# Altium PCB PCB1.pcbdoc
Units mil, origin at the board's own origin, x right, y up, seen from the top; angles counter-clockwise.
Board outline 5270 x 5080 mil, 2 copper layers (Top Layer, Bottom Layer); 23 components, 26 nets, 116 pads, 268 vias.
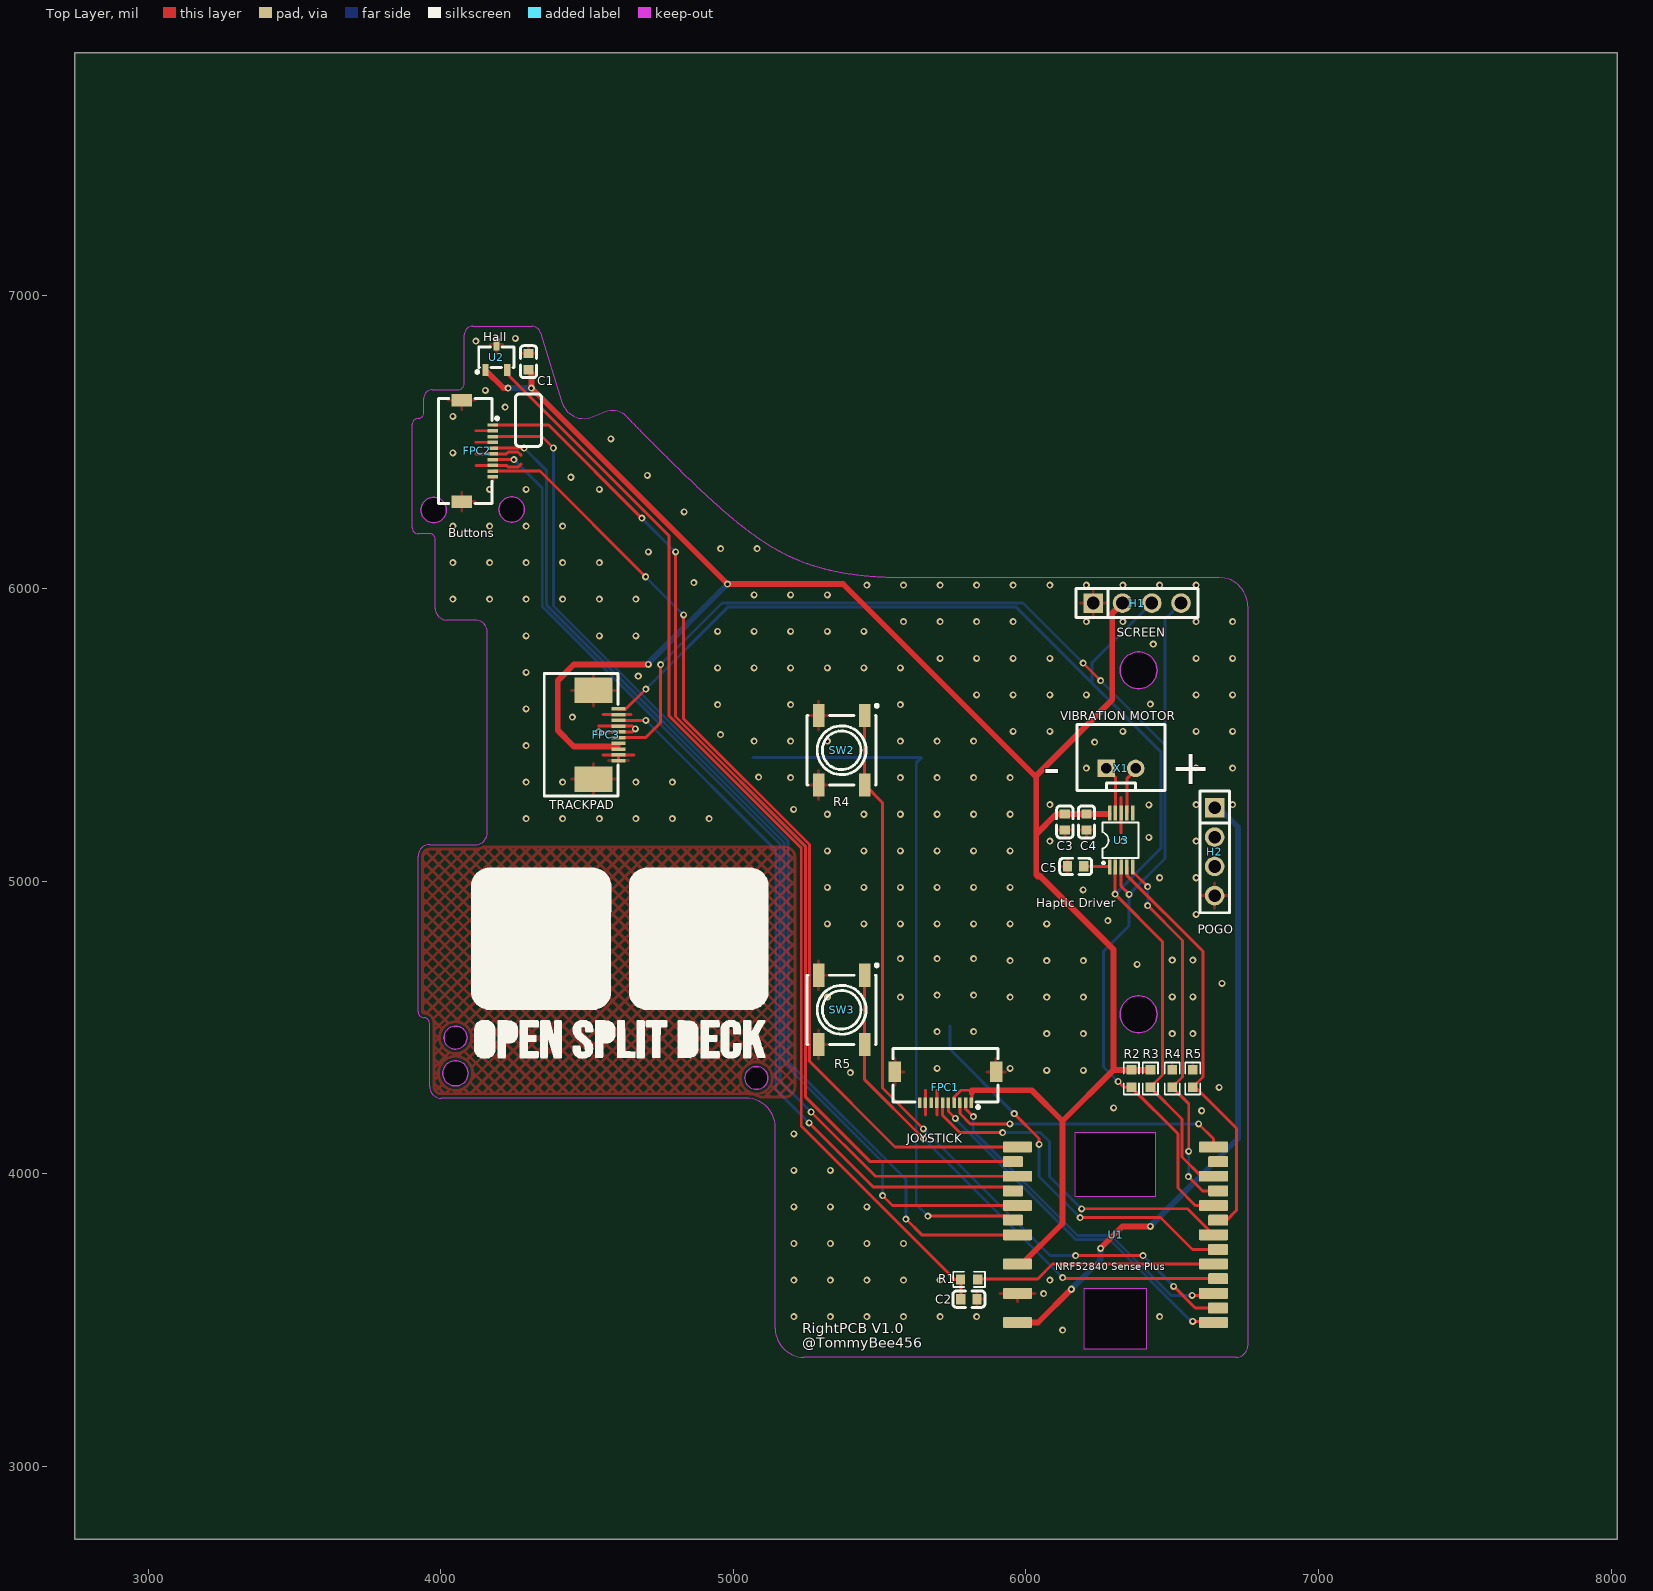
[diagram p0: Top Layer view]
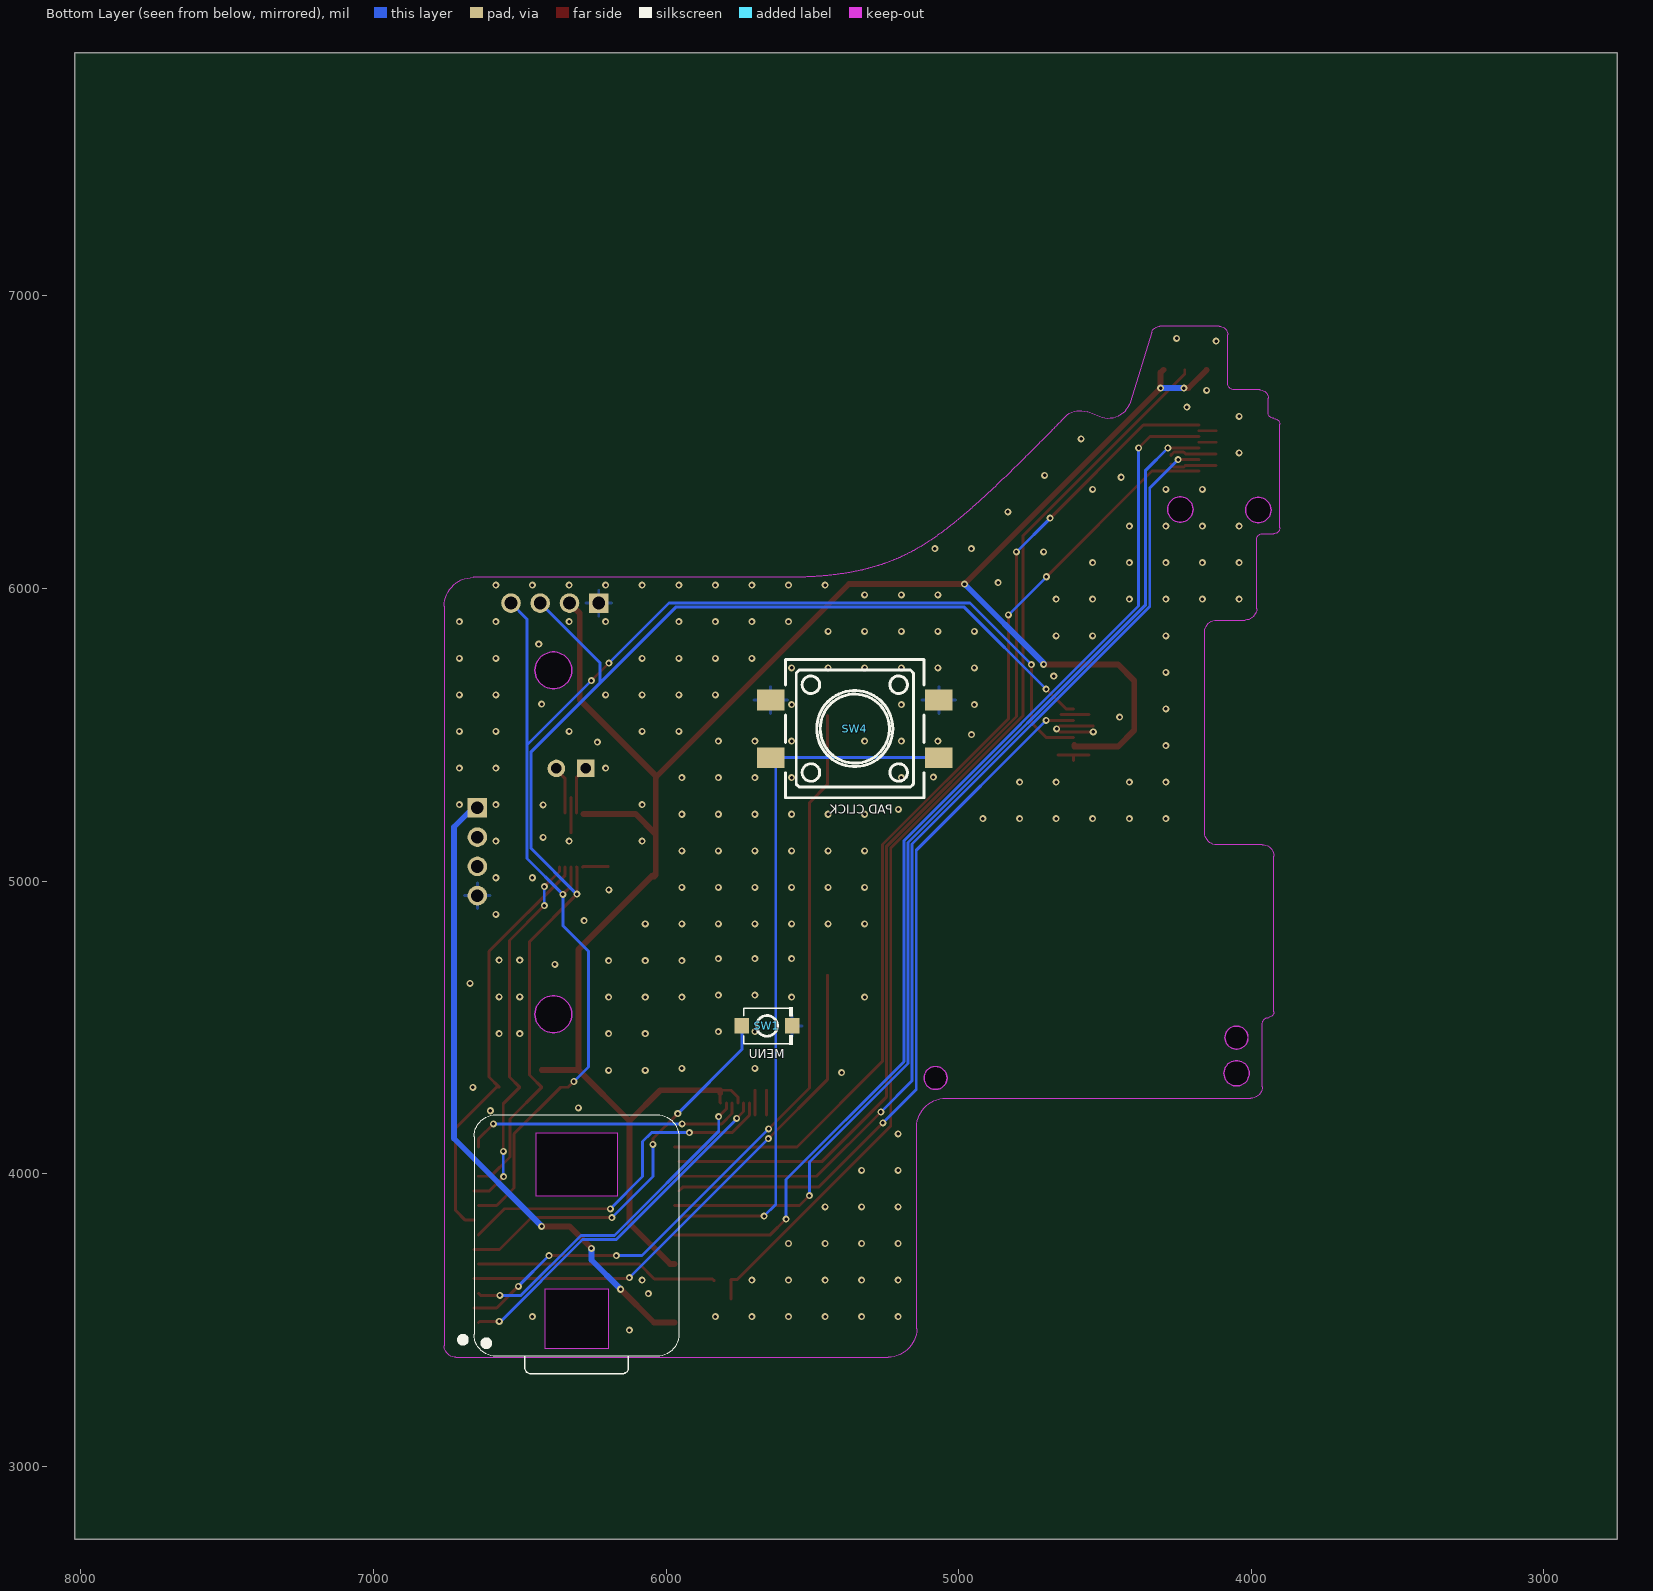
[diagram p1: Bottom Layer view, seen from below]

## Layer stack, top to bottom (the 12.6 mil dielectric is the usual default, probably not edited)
Top Layer: signal copper (thickness not stored)
Dielectric: dielectric 12.6, FR-4, Dk 4.8
Bottom Layer: signal copper (thickness not stored)

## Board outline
8020,2750 2750,2750 2750,7830 8020,7830
cut-out: 5118.27,4327 cw(c5078.9,4327) 5039.53,4327 cw(c5078.9,4327)
cut-out: 4019.01,6268 cw(c3975.7,6268) 3932.39,6268 cw(c3975.7,6268)
cut-out: 4093.71,4343 cw(c4050.4,4343) 4007.09,4343 cw(c4050.4,4343)
cut-out: 4285.61,6270 cw(c4242.3,6270) 4198.99,6270 cw(c4242.3,6270)
cut-out: 4089.77,4465 cw(c4050.4,4465) 4011.03,4465 cw(c4050.4,4465)
cut-out: 6448,5720 cw(c6385,5720) 6322,5720 cw(c6385,5720)
cut-out: 6448,4545 cw(c6385,4545) 6322,4545 cw(c6385,4545)

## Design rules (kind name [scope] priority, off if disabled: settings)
BoardOutlineClearance copperThickness1oz [All] p0: genericclearance=10 ignorepadtopadclearanceinfootprint=FALSE except(0: Arc-SplitContinuation Track-SplitContinuation SMDPad-SplitContinuation THPad-SplitContinuation Via-SplitContinuation Fill-SplitContinuation Poly-SplitContinuation Region-SplitContinuation Text-SplitContinuation; 6: Track-CutoutEdge SMDPad-CutoutEdge THPad-CutoutEdge Via-CutoutEdge Region-CutoutEdge; 11.8: Track-OutlineEdge SMDPad-OutlineEdge THPad-OutlineEdge Via-OutlineEdge Fill-OutlineEdge Region-OutlineEdge Poly-OutlineEdge Text-OutlineEdge Fill-CutoutEdge)
BoardOutlineClearance copperThickness2oz [All] p0: genericclearance=10 ignorepadtopadclearanceinfootprint=FALSE except(0: Arc-SplitContinuation Track-SplitContinuation SMDPad-SplitContinuation THPad-SplitContinuation Via-SplitContinuation Fill-SplitContinuation Poly-SplitContinuation Region-SplitContinuation Text-SplitContinuation; 6: Track-CutoutEdge SMDPad-CutoutEdge THPad-CutoutEdge Via-CutoutEdge Region-CutoutEdge; 11.8: Track-OutlineEdge SMDPad-OutlineEdge THPad-OutlineEdge Via-OutlineEdge Fill-OutlineEdge Region-OutlineEdge Poly-OutlineEdge Text-OutlineEdge Fill-CutoutEdge)
Clearance copperThickness1oz [(InNet('$1N1882') OR InNet('GND') OR InNet('3V3') OR InNet('+5V') OR InNet('STICKCLICK') OR InNet('STICKX') OR InNet('BUMPER') OR InNet('STICKY') OR InNet('START') OR InNet('SCL') OR InNet('SDA') OR InNet('P4') OR InNet('P5') OR InNet('TRIGGER') OR InNet('Y') OR InNet('X') OR InNet('B') OR InNet('A') OR InNet('MODE') OR InNet('HAPTIC_TRIG') OR InNet('DRV_EN') OR InNet('OUT+') OR InNet('OUT-') OR InNet('RDY') OR InNet('PAD_CLICK') OR InNet('$1N6654'))] p1: gap=7 ignorepadtopadclearanceinfootprint=FALSE except(4: Track-Track; 6: Track-SMDPad SMDPad-SMDPad Track-THPad SMDPad-THPad THPad-THPad Track-Via SMDPad-Via THPad-Via Via-Via SMDPad-Fill THPad-Fill Via-Fill Fill-Fill Track-Region SMDPad-Region THPad-Region Via-Region Region-Region Track-Poly SMDPad-Poly THPad-Poly Via-Poly Fill-Poly Region-Poly Poly-Poly Track-Text SMDPad-Text THPad-Text Via-Text Fill-Text Region-Text Poly-Text Text-Text; 6.9: Track-Hole SMDPad-Hole THPad-Hole Via-Hole Fill-Hole Region-Hole Poly-Hole Text-Hole Sheet-Hole; 11.8: Track-Fill Fill-Region Track-Sheet SMDPad-Sheet THPad-Sheet Via-Sheet Fill-Sheet Region-Sheet Poly-Sheet Text-Sheet)
Clearance copperThickness2oz [All] p1: gap=7 ignorepadtopadclearanceinfootprint=FALSE except(6: Track-SMDPad SMDPad-SMDPad Track-THPad SMDPad-THPad THPad-THPad Track-Via SMDPad-Via THPad-Via Via-Via SMDPad-Fill THPad-Fill Via-Fill Fill-Fill Track-Region SMDPad-Region THPad-Region Via-Region Region-Region Track-Poly SMDPad-Poly THPad-Poly Via-Poly Fill-Poly Region-Poly Poly-Poly Track-Text SMDPad-Text THPad-Text Via-Text Fill-Text Region-Text Poly-Text Text-Text; 6.9: Track-Hole SMDPad-Hole THPad-Hole Via-Hole Fill-Hole Region-Hole Poly-Hole Text-Hole Sheet-Hole; 8: Track-Track; 11.8: Track-Fill Fill-Region Track-Sheet SMDPad-Sheet THPad-Sheet Via-Sheet Fill-Sheet Region-Sheet Poly-Sheet Text-Sheet)
DiffPairsRouting differentialPair [All] p1: maxuncoupledlength=10 minlimit=6 maxlimit=6 mostfreqgap=6 toplayer_minwidth=5 toplayer_prefwidth=10 toplayer_maxwidth=100 bottomlayer_minwidth=5 bottomlayer_prefwidth=10 bottomlayer_maxwidth=100
PasteMaskExpansion pasteMaskExpansion [All] p1: expansion=0
PlaneConnect innerPlane [All] p1: planeconnectstyle=Relief reliefexpansion=20 reliefentries=4 reliefconductorwidth=10 reliefairgap=10
PolygonConnect copperRegion [All] p1: connectstyle=Relief reliefentries=4 reliefconductorwidth=10 polygonreliefangle="90 Angle" airgapwidth=10
RoutingVias viaSize [All] p1: viastyle="Through Hole" holewidth=12.0078 minholewidth=11.811 maxholewidth=248.0314 width=24.0158 minwidth=19.685 maxwidth=393.7008
SolderMaskExpansion solderMaskExpansion [All] p1: useseparateexpansions=TRUE expansion=2 expansionbottom=2
Width copperThickness1oz [All] p1: maxlimit=100 minlimit=5 preferedwidth=10
Width copperThickness2oz [All] p1: maxlimit=100 minlimit=8 preferedwidth=10

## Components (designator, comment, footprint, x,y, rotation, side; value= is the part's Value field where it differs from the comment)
C1 "CC0603KRX7R9BB104" C0603 4300,6775 r270 top
C2 "0603B472K500NT" C0603 5805,3571.21 r180 top
C3 "CC0603KRX7R9BB104" C0603 6133,5202 r90 top
C4 "CL10A106KP8NNNC" C0603 6207,5202 r90 top
C5 "CL10A105KB8NNNC" C0603 6170,5050 r0 top
FPC1 "FPC-05F-10PH15" FPC-SMD_10P-P0.50_XUNPU_FPC-05F-10PH15 5725,4295 r180 top
FPC2 "FPC-05F-10PH15" FPC-SMD_10P-P0.50_XUNPU_FPC-05F-10PH15 4125,6470 r270 top
FPC3 "AFC07-S10ECC-00" FPC-SMD_P0.50-10P_LCS-SJ-H2.0 4565,5500 r90 top
H1 "PM254V-11-04-H85" HDR-TH_4P-P2.54-V-F 6380,5950 r0 top
H2 "PM254V-11-04-H85" HDR-TH_4P-P2.54-V-F 6645,5100 r270 top
R1 "0603WAF1000T5E" R0603 5805.7,3638.95 r0 top
R2 "0603WAF2201T5E_C4190" R0603 6360,4325 r90 top
R3 "0603WAF2201T5E_C4190" R0603 6425,4325 r90 top
R4 "0603WAF2003T5E" R0603 6500,4325 r270 top
R5 "0603WAF2003T5E" R0603 6570,4325 r270 top
SW1 "Start" SW-SMD_L3.9-W3.0-P4.45 5655,4505 r180 bottom
SW2 "EVPBFAC1A000" KEY-SMD_4P-L6.0-W6.0-P4.00-LS6.6 5370,5447 r270 top
SW3 "EVPBFAC1A000" KEY-SMD_4P-L6.0-W6.0-P4.00-LS6.6 5370,4560 r270 top
SW4 "TS-1103S-C-I" KEY-SMD_4P-L12.0-W12.0-P5.00-LS15.4 5355,5520 r0 bottom
U1 "XIAO-nRF52840_Plus_SMD" XIAO-nRF52840-Plus-SMD 6305,3765 r180 top
U2 "A1304ELHLX-T" SOT-23-3_L3.0-W1.9-P0.95-LS2.9-BL 4190,6790 r0 top
U3 "DRV2605LDGSR" VSSOP-10_L3.0-W3.0-P0.50-LS4.9-BL 6325,5140 r0 top
X1 "JST" 2JST2.54 6325,5385 r0 top

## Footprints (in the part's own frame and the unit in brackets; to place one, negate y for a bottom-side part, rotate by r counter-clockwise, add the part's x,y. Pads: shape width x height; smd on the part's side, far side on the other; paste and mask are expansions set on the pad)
2JST2.54 [mil]
  rect 60x60 hole 36: 1(-50,0)
  round 60 hole 36: 2(50,0)
  silkscreen extent -150,-75 150,150
C0603 [mm]
  rect 0.8x0.9 smd: 1(-0.7,0) 2(0.7,0)
  silkscreen extent -1.39,-0.71 1.39,0.71
FPC-SMD_10P-P0.50_XUNPU_FPC-05F-10PH15 [mm]
  rect 0.3x0.9 smd: 1(-2.25,1.35) 2(-1.75,1.35) 3(-1.25,1.35) 4(-0.75,1.35) 5(-0.25,1.35) 6(0.25,1.35) 7(0.75,1.35) 8(1.25,1.35) 9(1.75,1.35) 10(2.25,1.35)
  rect 1.1x1.8 smd: 11(4.4,-1.35) 12(-4.4,-1.35)
  silkscreen extent -4.56,-3.36 4.55,1.84
FPC-SMD_P0.50-10P_LCS-SJ-H2.0 [mm]
  rect 0.3x1.2 smd: 1(2.25,-1.085) 2(1.75,-1.085) 3(1.25,-1.085) 4(0.75,-1.085) 5(0.25,-1.085) 6(-0.25,-1.085) 7(-0.75,-1.085) 8(-1.25,-1.085) 9(-1.75,-1.085) 10(-2.25,-1.085)
  rect 2.2x3.3 smd: 11(-3.85,1.085) 12(3.85,1.085)
  silkscreen extent -5.3,-1.04 5.3,5.37
HDR-TH_4P-P2.54-V-F [mm]
  rect 1.7x1.7 hole 1.1: 1(-3.81,0)
  round 1.7 hole 1.1: 2(-1.27,0) 3(1.27,0) 4(3.81,0)
  silkscreen extent -5.29,-1.27 5.29,1.27
KEY-SMD_4P-L6.0-W6.0-P4.00-LS6.6 [mm]
  rect 2x1 smd: 1(-3,2) 2(3,2) 3(-3,-2) 4(3,-2)
  silkscreen extent -3.99,-3 3,3.18
KEY-SMD_4P-L12.0-W12.0-P5.00-LS15.4 [mm]
  rect 2.4x1.8 smd: 1(-7.3,2.5) 2(7.3,2.5) 3(-7.3,-2.5) 4(7.3,-2.5)
  silkscreen extent -6,-6.02 6,5.98
R0603 [mil]
  rect 31.75x34.02 smd: 1(-29.66,0) 2(29.66,0)
  silkscreen extent -55,-26 55,26
SOT-23-3_L3.0-W1.9-P0.95-LS2.9-BL [mil]
  rect 20.95x40.85 smd: 1(-37.4,-43.36) 2(37.4,-43.36) 3(0.01,43.36)
  silkscreen extent -70,-55 60,35
SW-SMD_L3.9-W3.0-P4.45 [mm]
  rect 1.23x1.36 smd: 1(-2.185,0) 2(2.185,0)
  silkscreen extent -2.03,-1.62 2.25,1.62
VSSOP-10_L3.0-W3.0-P0.50-LS4.9-BL [mm]
  rect 0.3x1.3 smd: 1(-1,-2.35) 2(-0.5,-2.35) 3(0,-2.35) 4(0.5,-2.35) 5(1,-2.35) 6(1,2.35) 7(0.5,2.35) 8(0,2.35) 9(-0.5,2.35) 10(-1,2.35)
  silkscreen extent -1.62,-2.08 1.52,1.54
XIAO-nRF52840-Plus-SMD [mm]
  rrect20% 2.532x0.95 smd: 1(-8.533,6.958) 2(-8.533,4.418) 3(-8.533,1.878) 4(-8.533,-0.662) 5(-8.533,-3.202) 6(-8.533,-5.742) 7(-8.533,-8.282) 8(8.477,-8.282) 9(8.477,-5.742) 10(8.477,-3.202) 11(8.477,-0.662) 12(8.477,1.878) 13(8.477,4.418) 14(8.477,6.958)
  rrect20% 1.732x0.95 smd: 15(-8.933,5.688) 16(-8.933,3.148) 17(-8.933,0.608) 18(-8.933,-1.932) 19(-8.933,-4.472) 20(-8.933,-7.012) 21(8.877,-7.012) 22(8.877,-4.472) 23(8.877,-1.932)
  Board Outline Layer lines w0.025: 3.5,-4 3.5,-9.5 -3.5,-9.5 -3.5,-4 3.5,-4 ; 2.75,9.25 2.75,4 -2.75,4 -2.75,9.25 2.75,9.25
  Board Outline Layer region: -3.5,-9.5 3.5,-9.5 3.5,-4 -3.5,-4
  Board Outline Layer region: -2.75,4 2.75,4 2.75,9.25 -2.75,9.25
  Multi-Layer board cut-out: -3.5,-9.5 3.5,-9.5 3.5,-4 -3.5,-4
  Multi-Layer board cut-out: -2.75,4 2.75,4 2.75,9.25 -2.75,9.25

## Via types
v1: diameter 24.02, hole 12.01, Top Layer to Bottom Layer, 268 vias

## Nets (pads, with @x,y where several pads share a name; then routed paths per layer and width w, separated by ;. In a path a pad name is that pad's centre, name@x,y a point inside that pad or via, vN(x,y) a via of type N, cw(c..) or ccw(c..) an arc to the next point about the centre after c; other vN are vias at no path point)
3V3: C1.2 C3.2 C4.2 FPC1.1 FPC1.4 FPC3.7 FPC3.8 H1.2 R2.2 R3.2 U1.12 U2.1 U3.10 | length 7180.7
  Top Layer w10: FPC1.4 5754.53,4261.33 5778.2,4285 5815,4285 ; FPC1.1 5815,4243.27 5815,4275
  Top Layer w20: U2.1 4214.24,6685 v1(4230,6685) ; C1.2 4310,6737.44 v1(4310,6684.82) 4310.18,6684.82 v1(4980,6015) 5375,6015 6032.5,5357.5 6035,5360 ; FPC3.7@4605,5465 4605,5460 4455,5460 4400,5515 4400,5685 4455.64,5740.64 v1(4709.36,5740.64) ; 5815,4275 5815,4285 6020,4285 6125,4180 ; U1.12 5986.07,3691.07 6125,3830 6125,4180 ; U3.10@6282.66,5229.56 C4.2 C3.2 6104.56,5229.56 6035,5160 ; H1.2 6295,5915 6295,5620 6035,5360 ; R3.2 R2.2 6299.66,4354.66 ; 6035,5160 6035,5360 ; 6035,5160 6035,5020.83 6040.42,5015.42 6045,5020 6299.66,4765.34 6299.66,4354.66 ; 6125,4180 6299.66,4354.66
  Bottom Layer w10: v1@4309.82,6685 v1(4310,6684.82)
  Bottom Layer w20: v1(4230,6685) v1@4309.82,6685 ; v1(4709.36,5740.64) 4709.36,5744.36 v1(4980,6015)
$1N1882: C5.2 U3.1 | length 89.1
  Top Layer w10: C5.2 6283.11,5050 U3.1
$1N6654: R1.2 U1.3 | length 829.2
  Top Layer w10: R1.2@5835.36,3633.95 5841.41,3640 6040,3640 6091.07,3691.07 U1.3
+5V: H2.1 U1.14 | length 2209.6
  Top Layer w20: U1.14 6041.07,3491.07 v1(6155,3605) ; v1(6255,3745) 6330,3820 v1(6425,3820)
  Bottom Layer w20: v1(6155,3605) 6255,3705 v1(6255,3745) ; v1(6425,3820) 6725,4120 6725,5185 6660,5250 H2.1
A: FPC2.7 U1.9 | length 3518.5
  Top Layer w10: FPC2.7 4178.62,6440 v1(4250,6440) ; v1(5265.75,4210.75) 5485.43,3991.07 U1.9
  Bottom Layer w10: v1(4250,6440) 4346.92,6343.08 4346.92,5938.44 5159.02,5126.34 5159.02,4317.48 v1@5265.75,4210.75
B: FPC2.3 U1.11 | length 3760.8
  Top Layer w10: FPC2.3 4345.79,6519.21 v1(4385,6480) ; v1(5590,3845) 5643.93,3791.07 U1.11
  Bottom Layer w10: v1(4385,6480) 4385,5940 5187.05,5137.95 5187.05,4382.77 5590,3979.82 v1(5590,3845)
BUMPER: FPC1.3 U1.7 | length 966.7
  Top Layer w10: FPC1.3 5774.21,4205.79 5810,4170 v1(5945,4170) ; v1(6590,4170) 6640.93,4119.07 U1.7
  Bottom Layer w10: v1(5945,4170) v1(6590,4170)
DRV_EN: R4.2 U1.19 U3.5 | length 1288.4
  Top Layer w10: U3.5 6364.38,5032.97 v1(6416.17,4981.17) ; v1(6416.15,4916.15) 6535,4797.31 6535,4330.34 R4.2 6556.26,4239.08 v1(6556.26,4076.26) ; v1(6555,3990) 6603.93,3941.07 U1.19
  Bottom Layer w10: v1(6416.15,4916.15) v1(6416.17,4981.17) ; v1(6555,3990) 6556.26,3991.26 v1(6556.26,4076.26)
GND: C1.1 C2.1 C3.1 C4.1 C5.1 FPC1.7 FPC1.9 FPC1.11 FPC1.12 FPC2.2 FPC2.4 FPC2.6 FPC2.8 FPC2.10 FPC2.11 FPC2.12 FPC3.2 FPC3.4 FPC3.5 FPC3.9 FPC3.10 FPC3.11 FPC3.12 H1.1 H2.4 R4.1 R5.1 SW1.2 SW2.3 SW2.4 SW3.3 SW3.4 SW4.3 SW4.4 U1.13 U2.3 U3.8 | length 1207.6
  Top Layer w10: 4120,6420.79 FPC2.8 4224.21,6420.79 4229.89,6415.11 4265.11,6415.11 4275,6425 ; 4120,6460.16 FPC2.6 4225.16,6460.16 4230.98,6465.98 4264.02,6465.98 4275,6455 ; 4120,6499.53 FPC2.4 ; 4120,6538.9 FPC2.2 ; v1(4540,5510) 4540.15,5509.85 FPC3.5 4654.85,5509.85 v1(4665,5520) 4655.47,5529.53 FPC3.4 4540,5529.53 ; 4555,5431.1 FPC3.9 ; 4555,5568.9 FPC3.2 4650,5568.9 ; FPC3.10 FPC3.9 ; 4660,5431.1 FPC3.9 ; 5656.1,4200 FPC1.9 5656.1,4285 ; 5695.47,4200 FPC1.7 5695.47,4285 ; 6325,5165 U3.8 6325,5285
  other v1: 6125,3465 5206.49,3511.34 5331.49,3511.34 5456.49,3511.34 5581.49,3511.34 5706.49,3511.34 5831.49,3511.34 6456.49,3511.34 6060,3590 5206.49,3636.34 5331.49,3636.34 5456.49,3636.34 5581.49,3636.34 5706.49,3636.34 6081.49,3636.34 5206.49,3761.34 5331.49,3761.34 5456.49,3761.34 5581.49,3761.34 5206.49,3886.34 5331.49,3886.34 5456.49,3886.34 5206.49,4011.34 5331.49,4011.34 5206.49,4136.34 6600,4215 6300,4225 6660,4295 5400,4345 6071.11,4353.29 6196.11,4353.29 5696.11,4360.17 5946.11,4360.17 6071.11,4478.29 6196.11,4478.29 6500,4478.3 6570.53,4478.3 5696.11,4485.17 5821.11,4485.17 5321.11,4603.29 5571.11,4603.29 5946.11,4603.29 6071.11,4603.29 6196.11,4603.29 6500,4603.91 6570.53,4603.91 5696.11,4610.17 5821.11,4610.17 6670,4650 6380,4715 5946.11,4728.29 6071.11,4728.29 6196.11,4728.29 6500,4730 6570.53,4730 5571.11,4735.17 5696.11,4735.17 5821.11,4735.17 5321.11,4853.29 5446.11,4853.29 5571.11,4853.29 5696.11,4853.29 5821.11,4853.29 5946.11,4853.29 6071.11,4853.29 6280,4865 6581.49,4886.34 6195,4970 5321.11,4978.29 5446.11,4978.29 5571.11,4978.29 5696.11,4978.29 5821.11,4978.29 5946.11,4978.29 6456.49,5011.34 6581.49,5011.34 5321.11,5103.29 5446.11,5103.29 5571.11,5103.29 5696.11,5103.29 5821.11,5103.29 5946.11,5103.29 6081.49,5136.34 6331.49,5136.34 6581.49,5136.34 6420,5149.2 4291.86,5213.23 4416.86,5213.23 4541.86,5213.23 4666.86,5213.23 4791.86,5213.23 4916.86,5213.23 5321.11,5228.29 5446.11,5228.29 5571.11,5228.29 5696.11,5228.29 5821.11,5228.29 5946.11,5228.29 5206.11,5245.17 6420,5260 6081.49,5261.34 6581.49,5261.34 6706.49,5261.34 4291.86,5338.23 4416.86,5338.23 4666.86,5338.23 4791.86,5338.23 5196.11,5353.29 5571.11,5353.29 5696.11,5353.29 5821.11,5353.29 5946.11,5353.29 5086.11,5355.17 6206.49,5386.34 6581.49,5386.34 6706.49,5386.34 4291.86,5463.23 6235,5475 5071.11,5478.29 5196.11,5478.29 5321.11,5478.29 5571.11,5478.29 5696.11,5478.29 5821.11,5478.29 4956.11,5500.17 5956.49,5511.34 6081.49,5511.34 6331.49,5511.34 6581.49,5511.34 6706.49,5511.34 4450,5560 4291.86,5588.23 4946.11,5603.29 5196.11,5603.29 5571.11,5603.29 6425,5605 5831.49,5636.34 5956.49,5636.34 6081.49,5636.34 6206.49,5636.34 6581.49,5636.34 6706.49,5636.34 4675,5700 4291.86,5713.23 4946.11,5728.29 5071.11,5728.29 5196.11,5728.29 5321.11,5728.29 5446.11,5728.29 5571.11,5728.29 5706.49,5761.34 5831.49,5761.34 5956.49,5761.34 6081.49,5761.34 6581.49,5761.34 6706.49,5761.34 6435,5810 4291.86,5838.23 4541.86,5838.23 4666.86,5838.23 4946.11,5853.29 5071.11,5853.29 5196.11,5853.29 5321.11,5853.29 5446.11,5853.29 5581.49,5886.34 5706.49,5886.34 5831.49,5886.34 5956.49,5886.34 6206.49,5886.34 6331.49,5886.34 6581.49,5886.34 6706.49,5886.34 4041.86,5963.23 4166.86,5963.23 4291.86,5963.23 4416.86,5963.23 4541.86,5963.23 4666.86,5963.23 5071.11,5978.29 5196.11,5978.29 5321.11,5978.29 5456.49,6011.34 5581.49,6011.34 5706.49,6011.34 5831.49,6011.34 5956.49,6011.34 6081.49,6011.34 6206.49,6011.34 6331.49,6011.34 6456.49,6011.34 6581.49,6011.34 4865,6020 4041.86,6088.23 4166.86,6088.23 4291.86,6088.23 4416.86,6088.23 4541.86,6088.23 4710,6125 4956.49,6136.34 5081.49,6136.34 4041.86,6213.23 4166.86,6213.23 4291.86,6213.23 4416.86,6213.23 4831.49,6261.34 4166.86,6338.23 4291.86,6338.23 4541.86,6338.23 4445,6380 4706.49,6386.34 4041.86,6463.23 4581.49,6511.34 4041.86,6588.23 4220,6620 4152.6,6676.98 4120,6845 4255,6855
HAPTIC_TRIG: R5.2 U1.18 U3.4 | length 1440
  Top Layer w10: U3.4 6344.69,5020.14 6605,4759.82 6605,4330.34 R5.2 6579.66,4295.34 6720,4155 6720,3875 6686.07,3841.07 U1.18
MODE: SW1.1 U1.17 | length 1355.7
  Top Layer w10: v1(5960,4205) 6045,4120 v1(6045,4100) ; v1(6185,3850) 6460,3850 6568.93,3741.07 U1.17
  Bottom Layer w10: SW1.1 5741.02,4423.98 v1(5960,4205) ; v1(6045,4100) 6045,3990 v1(6185,3850)
OUT+: U3.7 X1.2 | length 167.1
  Top Layer w10: U3.7 6344.69,5349.69 X1.2@6380,5385
OUT-: U3.9 X1.1 | length 165
  Top Layer w10: X1.1 6305.31,5354.69 U3.9
P4: SW2.1 SW2.2 U1.15 | length 2755.9
  Top Layer w10: SW2.1 SW2.2 5510,5267.63 5510,4292.52 v1(5649.63,4152.89) ; v1(6170,3720) v1(6400,3720) ; v1(6505,3615) 6578.93,3541.07 U1.15
  Bottom Layer w10: v1(5649.63,4152.89) 6082.52,3720 v1(6170,3720) ; v1(6400,3720) v1(6505,3615)
P5: SW3.1 SW3.2 U1.16 | length 1846.5
  Top Layer w10: SW3.1 SW3.2 5448.74,4321.26 v1(5650,4120) ; v1(6125,3645) 6128.93,3641.07 U1.16
  Bottom Layer w10: v1(5650,4120) v1(6125,3645)
PAD_CLICK: SW4.1 SW4.2 U1.23 | length 2461.4
  Top Layer w10: v1(5665,3855) 5941.57,3855 U1.23
  Bottom Layer w10: SW4.1 SW4.2 5625,5404.18 5625,3895 v1(5665,3855)
RDY: FPC3.3 U1.22 | length 2492.8
  Top Layer w10: FPC3.3 4608.18,5548.76 v1(4701.24,5548.76) ; v1(5258.76,4173.76) 5477.52,3955 5941.57,3955 U1.22
  Bottom Layer w10: v1(4701.24,5548.76) 5145,5105 5145,4287.52 v1(5258.76,4173.76)
SCL: FPC3.1 H1.3 R3.1 U1.6 U3.2 | length 4365.6
  Top Layer w10: FPC3.1 4633.59,5588.59 v1(4701.26,5656.26) ; U3.2 6305,5047.16 v1(6305,4955) 6467.07,4792.93 6467.07,4337.07 6460,4330 6459.66,4330 R3.1 6533.27,4187.07 6533.27,4056.73 6598.93,3991.07 U1.6
  Bottom Layer w10: v1(4701.26,5656.26) 4980.98,5935.98 5967.07,5935.98 6225,5678.06 ; v1(6305,4955) 6460.98,5110.98 6460.98,5442.07 6225,5678.06 ; H1.3 6225,5745 6225,5678.06
SDA: FPC3.6 H1.4 R2.1 U1.5 U3.3 | length 4855
  Top Layer w10: FPC3.6 4689.84,5490.16 4690,5490 4700,5490 4751.24,5541.24 v1(4751.24,5740) ; v1(6195,5745) v1(6255,5685) ; v1(6315,4315) 6334.66,4295.34 R2.1 6519.25,4136.09 6519.25,3950.75 6578.93,3891.07 U1.5 ; U3.3 6325,4982.52 v1(6352.75,4954.76)
  Bottom Layer w10: v1(4751.24,5740) 4961.24,5950 5990,5950 v1(6195,5745) ; v1(6255,5685) 6475,5465 ; v1(6315,4315) 6265,4365 6265,4760 6352.75,4847.75 v1(6352.75,4954.76) 6475,5077.01 6475,5465 ; H1.4 6475,5895 6475,5465
START: FPC2.9 U1.8 | length 3392.1
  Top Layer w10: FPC2.9 4338.9,6401.1 v1(4700,6040) ; v1(4829.94,5909.53) 4829.94,5554.7 5260,5124.64 5260,4383.84 5552.77,4091.07 U1.8
  Bottom Layer w10: v1(4700,6040) 4700,6039.47 v1(4829.94,5909.53)
STICKCLICK: FPC1.6 U1.4 | length 1207.8
  Top Layer w10: FPC1.6 5715,4241.69 5715,4199.97 5774.97,4140 v1(5920,4140) ; v1(6190,3880) 6552,3880 6611.6,3820.4 6611.6,3820.01 6620.23,3811.38 6620.62,3811.38 U1.4
  Bottom Layer w10: v1(5920,4140) 6050,4140 6080,4110 6080,3990 v1(6190,3880)
STICKX: FPC1.5 U1.1 | length 1235.6
  Top Layer w10: FPC1.5 5734.84,4212.65 v1(5758.74,4188.74) ; v1(6570,3495) 6637,3495 U1.1
  Bottom Layer w10: v1(5758.74,4188.74) 5758.74,4186.26 6170,3775 6285.18,3775 6565.18,3495 v1(6570,3495)
STICKY: FPC1.2 U1.2 | length 1163.7
  Top Layer w10: FPC1.2 5793.9,4221.1 v1(5820,4195) ; v1(6568.22,3584.29) 6634.15,3584.29 U1.2
  Bottom Layer w10: v1(5820,4195) 5820,4145 6175.98,3789.02 6290.98,3789.02 6495.71,3584.29 v1(6568.22,3584.29)
TRIGGER: C2.2 R1.1 U2.2 | length 3829.2
  Top Layer w10: U2.2 4227.4,6732.6 4780,6180 4780,5565 5231.97,5113.03 5231.97,4163.03 5756.05,3638.95 R1.1 5777.44,3637.55 C2.2
X: FPC2.5 U1.10 | length 3644.5
  Top Layer w10: FPC2.5 4178.31,6480 v1(4284.91,6480) ; v1(5510,3925) 5543.93,3891.07 U1.10
  Bottom Layer w10: v1@4285,6480 4360.93,6404.07 4360.93,5944.24 5173.03,5132.15 5173.03,4376.97 5510,4040 v1(5510,3925)
Y: FPC2.1 U1.21 | length 3652.2
  Top Layer w10: FPC2.1 4368.91,6558.58 v1(4687.25,6240.24) ; v1(4802.99,6125) 4802.01,6124.02 4802.01,5562.81 5245.98,5118.84 5245.98,4263.03 5467.95,4041.07 U1.21
  Bottom Layer w10: v1(4687.25,6240.24) 4802.48,6125 v1(4802.99,6125)
pads on no net: FPC1.8 FPC1.10 H2.2 H2.3 U1.20 U3.6

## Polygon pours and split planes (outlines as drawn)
GND on Top Layer (hatched 45Degree grid 30 track 10, pour order 0): 3960.39,5122 5175.39,5122 cw(c5175.39,5082) 5215.39,5082 5215.39,4297 cw(c5175.39,4297) 5175.39,4257 3960.39,4257 cw(c3960.39,4297) 3920.39,4297 3920.39,5082 cw(c3960.39,5082)
GND on Bottom Layer (solid, remove dead copper, pour order 4): 7470,3000 3340,3000 3000,3340 3000,6975 3255,7230 7495,7230 7770,6955 7770,3300
GND on Top Layer (solid, remove dead copper, pour order 2): 6890,6175 6890,3275 6815,3200 4950,3200 4959.42,4260 5183.22,4260 5208.28,4273.8 5210,4285.48 5210,5085 5198.56,5108.28 5179.33,5115.21 4029.71,5115.21 3680,5471.23 3680,7580 5485,7580

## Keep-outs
Board Outline Layer:
  circle w1: c5078.9,4327 r39.37
  region: 5118.27,4327 cw(c5078.9,4327) 5039.53,4327 cw(c5078.9,4327)
  circle w1: c3975.7,6268 r43.31
  region: 4019.01,6268 cw(c3975.7,6268) 3932.39,6268 cw(c3975.7,6268)
  circle w1: c4050.4,4343 r43.31
  region: 4093.71,4343 cw(c4050.4,4343) 4007.09,4343 cw(c4050.4,4343)
  circle w1: c4242.3,6270 r43.31
  region: 4285.61,6270 cw(c4242.3,6270) 4198.99,6270 cw(c4242.3,6270)
  circle w1: c4050.4,4465 r39.37
  region: 4089.77,4465 cw(c4050.4,4465) 4011.03,4465 cw(c4050.4,4465)
  circle w1: c6385,5720 r63
  region: 6448,5720 cw(c6385,5720) 6322,5720 cw(c6385,5720)
  circle w1: c6385,4545 r63
  region: 6448,4545 cw(c6385,4545) 6322,4545 cw(c6385,4545)
  lines w3.9: 6127.83,3372.24 6482.16,3372.24
  lines w3.94: 6127.83,3372.24 5241.34,3372.24 cw(c5241.34,3470.66) 5142.91,3470.66 5142.91,4159.64 ccw(c5044.49,4159.64) 5044.49,4258.06 4001.18,4258.06 cw(c4001.18,4297.43) 3961.81,4297.43 3961.81,4513.97 ccw(c3942.13,4513.97) 3942.13,4533.65 cw(c3942.13,4553.34) 3922.44,4553.34 3922.44,5084.84 cw(c3961.81,5084.84) 3961.81,5124.21 4119.29,5124.21 ccw(c4119.29,5163.58) 4158.66,5163.58 4158.66,5852.55 ccw(c4119.29,5852.55) 4119.29,5891.92 4020.87,5891.92 cw(c4020.87,5931.29) 3981.5,5931.29 3981.5,6167.51 ccw(c3961.81,6167.51) 3961.81,6187.2 3922.44,6187.2 cw(c3922.44,6206.88) 3902.76,6206.88 3902.76,6561.21 cw(c3922.44,6561.21) 3922.44,6580.9 ccw(c3922.44,6600.58) 3942.13,6600.58 3942.13,6649.8 cw(c3971.65,6649.8) 3971.65,6679.32 4060.24,6679.32 ccw(c4060.24,6699.01) 4079.92,6699.01 4079.92,6866.33 cw(c4109.45,6866.33) 4109.45,6895.86 4311.95,6895.86 cw(c4311.95,6866.33) 4340.16,6875.05 4413.98,6636.22 ccw(c4489.21,6659.47) 4517.93,6586.16 4561.13,6603.08 cw(c4586.26,6538.93) 4635.65,6586.97 4640.18,6582.32 4644.68,6577.69 4649.16,6573.09 4653.62,6568.52 4658.06,6563.97 4662.48,6559.45 4666.88,6554.96 4671.25,6550.49 4675.61,6546.05 4679.94,6541.63 4684.25,6537.24 4688.54,6532.88 4692.8,6528.54 4697.05,6524.23 4701.27,6519.94 4705.48,6515.68 4709.66,6511.45 4713.82,6507.24 4717.96,6503.05 4722.08,6498.9 4726.18,6494.76 4730.26,6490.66 4734.31,6486.58 4738.35,6482.52 4742.37,6478.49 4746.36,6474.49 4750.34,6470.51 4754.29,6466.55 4758.22,6462.63 4762.14,6458.72 4766.03,6454.84 4769.9,6450.99 4773.76,6447.16 4777.59,6443.36 4781.4,6439.58 4785.2,6435.82 4788.97,6432.09 4792.73,6428.39 4796.46,6424.7 4800.18,6421.05 4803.88,6417.41 4807.56,6413.81 4811.22,6410.22 4814.86,6406.66 4818.48,6403.12 4822.09,6399.61 4825.67,6396.12 4829.24,6392.66 4832.79,6389.21 4836.32,6385.8 4839.84,6382.4 4843.33,6379.03 4846.81,6375.68 4850.27,6372.35 4853.72,6369.05 4857.14,6365.77 4860.55,6362.51 4863.95,6359.28 4867.32,6356.07 4870.68,6352.88 4874.03,6349.71 4877.36,6346.56 4880.67,6343.44 4883.96,6340.34 4887.24,6337.26 4890.51,6334.2 4893.76,6331.17 4896.99,6328.16 4900.21,6325.16 4903.42,6322.19 4906.61,6319.24 4909.78,6316.31 4912.94,6313.41 4916.09,6310.52 4919.22,6307.66 4922.34,6304.81 4925.44,6301.99 4928.53,6299.18 4931.61,6296.4 4934.67,6293.64 4937.72,6290.9 4940.76,6288.18 4943.79,6285.47 4946.8,6282.79 4949.8,6280.13 4952.79,6277.49 4955.77,6274.86 4958.73,6272.26 4961.69,6269.68 4964.63,6267.11 4967.56,6264.57 4970.48,6262.04 4973.39,6259.53 4976.29,6257.04 4979.17,6254.57 4982.05,6252.12 4984.92,6249.69 4987.77,6247.28 4990.62,6244.88 4993.46,6242.5 4996.29,6240.15 4999.11,6237.8 5001.92,6235.48 5004.72,6233.18 5007.51,6230.89 5010.3,6228.62 5013.08,6226.37 5015.84,6224.13 5018.61,6221.91 5021.36,6219.71 5024.1,6217.53 5026.84,6215.36 5029.58,6213.21 5032.3,6211.08 5035.02,6208.97 5037.73,6206.87 5040.44,6204.78 5043.14,6202.72 5045.83,6200.67 5048.52,6198.64 5051.2,6196.62 5053.88,6194.62 5056.55,6192.63 5059.22,6190.66 5061.88,6188.71 5064.54,6186.77 5067.2,6184.85 5069.85,6182.94 5072.5,6181.05 5075.14,6179.18 5077.78,6177.31 5080.42,6175.47 5083.05,6173.64 5085.68,6171.82 5088.31,6170.02 5090.94,6168.24 5093.56,6166.47 5096.18,6164.71 5098.8,6162.97 5101.42,6161.24 5104.04,6159.53 5106.66,6157.83 5109.27,6156.15 5111.89,6154.48 5114.5,6152.82 5117.12,6151.18 5119.73,6149.56 5122.35,6147.94 5124.96,6146.34 5127.57,6144.76 5130.19,6143.18 5132.81,6141.62 5135.43,6140.08 5138.04,6138.55 5140.66,6137.03 5143.29,6135.53 5145.91,6134.03 5148.54,6132.56 5151.17,6131.09 5153.8,6129.64 5156.43,6128.2 5159.07,6126.77 5161.71,6125.36 5164.35,6123.96 5167,6122.57 5169.65,6121.19 5172.31,6119.83 5174.97,6118.48 5177.63,6117.15 5180.3,6115.82 5182.97,6114.51 5185.65,6113.21 5188.33,6111.92 5191.02,6110.64 5193.72,6109.38 5196.42,6108.13 5199.12,6106.89 5201.83,6105.66 5204.55,6104.45 5207.28,6103.24 5210.01,6102.05 5212.75,6100.87 5215.49,6099.71 5218.25,6098.55 5221.01,6097.41 5223.78,6096.27 5226.56,6095.15 5229.34,6094.04 5232.13,6092.94 5234.94,6091.86 5237.75,6090.78 5240.57,6089.72 5243.39,6088.67 5246.23,6087.63 5249.08,6086.6 5251.94,6085.58 5254.8,6084.57 5257.68,6083.58 5260.57,6082.59 5263.47,6081.62 5266.38,6080.66 5269.3,6079.71 5272.23,6078.77 5275.17,6077.84 5278.12,6076.92 5281.09,6076.01 5284.06,6075.12 5287.05,6074.23 5290.05,6073.36 5293.06,6072.49 5296.09,6071.64 5299.13,6070.8 5302.18,6069.97 5305.24,6069.15 5308.32,6068.34 5311.41,6067.54 5314.51,6066.75 5317.63,6065.97 5320.76,6065.21 5323.91,6064.45 5327.07,6063.7 5330.24,6062.97 5333.43,6062.25 5336.63,6061.53 5339.85,6060.83 5343.08,6060.14 5346.33,6059.46 5349.6,6058.78 5352.87,6058.12 5356.17,6057.47 5359.48,6056.83 5362.81,6056.2 5366.15,6055.58 5369.51,6054.98 5372.88,6054.38 5376.27,6053.79 5379.68,6053.21 5383.11,6052.65 5386.55,6052.09 5390.01,6051.54 5393.49,6051.01 5396.98,6050.48 5400.49,6049.97 5404.02,6049.47 5407.57,6048.97 5411.13,6048.49 5414.72,6048.02 5418.32,6047.55 5421.94,6047.1 5425.57,6046.66 5429.23,6046.23 5432.91,6045.81 5436.6,6045.4 5440.31,6044.99 5444.05,6044.6 5447.8,6044.23 5451.57,6043.86 5455.36,6043.5 5459.17,6043.15 5463,6042.81 5466.84,6042.48 5470.71,6042.17 5474.6,6041.86 5478.51,6041.56 5482.44,6041.28 5486.39,6041 5490.36,6040.73 5494.34,6040.48 5498.35,6040.23 5502.38,6040 5506.43,6039.78 5510.51,6039.56 5514.6,6039.36 5518.71,6039.17 5522.84,6038.98 5527,6038.81 5531.17,6038.65 5535.37,6038.5 5539.59,6038.36 5543.82,6038.23 5548.08,6038.11 5552.36,6038 5556.66,6037.9 5560.99,6037.81 5565.33,6037.73 5569.7,6037.66 5574.08,6037.61 5578.49,6037.56 5582.92,6037.52 5587.37,6037.5 5591.84,6037.48 5596.34,6037.48 6659.33,6037.48 cw(c6659.33,5939.05) 6757.76,5939.05 6757.76,3411.61 cw(c6718.39,3411.61) 6718.39,3372.24 6482.16,3372.24

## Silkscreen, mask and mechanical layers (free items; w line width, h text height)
Top Silkscreen Layer:
  drawing of 32 lines, arcs and shapes, not listed
  text "Hall" at 4145,6845 h30
  text "Buttons" at 4025,6175 h30
  text "SCREEN" at 6310,5835 h30
  text "VIBRATION MOTOR" at 6117,5550 h30
  text "-" at 6059.92,5330 h120
  text "+" at 6495,5330 h120
  text "R4" at 5342,5255 h30
  text "TRACKPAD" at 4370,5245 h30
  text "Haptic Driver" at 6035,4910 h30
  text "POGO" at 6587,4820 h30
  text "R5" at 5345,4360 h30
  text "JOYSTICK" at 5592,4105 h30
  text "NRF52840 Sense Plus" at 6100,3670 h25
  text "RightPCB V1.0" at 5235,3455 h35
  text "@TommyBee456" at 5235,3405 h35
Bottom Silkscreen Layer:
  text "PAD CLICK" at 5225,5230 h30
  text "MENU" at 5595,4395 h30
Mechanical Layer:
  circle w1: c5078.9,4327 r39.37
  circle w1: c3975.7,6268 r43.31
  circle w1: c4050.4,4343 r43.31
  circle w1: c4242.3,6270 r43.31
  circle w1: c4050.4,4465 r39.37
  circle w1: c6385,5720 r63
  circle w1: c6385,4545 r63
